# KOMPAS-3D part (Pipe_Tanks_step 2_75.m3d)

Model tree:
1. X Axis
2. Y Axis
3. Z Axis  (labels: T-Bend Dn 50; Pipe Dn 50)
     Òîëùèíà ñòåíêè 1 = 1

Referenced files in C:\Documents and Settings\kashirsky\Мои документы\Camtasia Studio\Pipelines3D\Tanks\: Tanks_step 4.a3d
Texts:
  Pipe Dn 50
  Steel ASTM A295
  Three Point Plane
  Plane at Angle
  Line and Point Plane
  Axis through Two Vertices
  Axis of Feature
  Axis of Conical Surface
  Axis through Edge
  Trim by Surface
  Trim by Sketch
  Feature with No History
  Intersection Axis of Two Planes
  Two Line Plane
  Line and Face Plane
  Bend by line
  Hole in sheet body
  Cut in sheet body
  Point in CM
  Linear Dimension from Line to Point
  Surface Finish Symbol
  Geometric Tolerance Symbol
  Leader #1
  Leader #2
  Leader #3
  Shape Deviations and Datum
  Node point number
  Mark of coordination axis
  Node point designation
  Mark/Reference designation with leader
  Mark/reference designation on line
  Mark/Reference designation without leader
  T-Bend Dn 50
  Plane of section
